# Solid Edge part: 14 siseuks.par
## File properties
Author: Henri
Template: Normal.par
Last saved by: Henri
Revision: 1
Application: Solid Edge
Accuracy: 0,990
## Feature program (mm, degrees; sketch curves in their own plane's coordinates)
sketch for "unnamed Protrusion 1" plane through (0, 0, 0) normal (1, 0, 0) x-axis (0, 1, 0)
  line (-25, -42.5) -> (-25, 54.5)
  arc centre (-22, 54.5) radius 3 from (-25, 54.5) to (-22, 57.5) cw
  line (-22, 57.5) -> (22, 57.5)
  arc centre (22, 54.5) radius 3 from (22, 57.5) to (25, 54.5) cw
  line (25, 54.5) -> (25, -42.5)
  line (25, -42.5) -> (-25, -42.5)
extrude "unnamed Protrusion 1" add finite 2.5 along +normal
sketch for "unnamed Cutout 1" plane through (2.5, 0, 0) normal (1, 0, 0) x-axis (0, 1, 0)
  line (-15, 41.5) -> (-15, 46)
  arc centre (-13.5, 46) radius 1.5 from (-15, 46) to (-13.5, 47.5) cw
  line (-13.5, 47.5) -> (13.5, 47.5)
  arc centre (13.5, 46) radius 1.5 from (13.5, 47.5) to (15, 46) cw
  line (15, 46) -> (15, 41.5)
  arc centre (13.5, 41.5) radius 1.5 from (13.5, 40) to (15, 41.5) ccw
  line (13.5, 40) -> (-13.5, 40)
  arc centre (-13.5, 41.5) radius 1.5 from (-15, 41.5) to (-13.5, 40) ccw
extrude "unnamed Cutout 1" cut through along -normal
sketch for "ExtrudedCutout_2" #1 plane through (2.5, 0, 0) normal (1, 0, 0) x-axis (0, 1, 0)
  line (14, 10) -> (-14, 10)
  arc centre (-14, 11) radius 1 from (-15, 11) to (-14, 10) ccw
  line (-15, 11) -> (-15, 34)
  arc centre (-14, 34) radius 1 from (-15, 34) to (-14, 35) cw
  line (-14, 35) -> (14, 35)
  arc centre (14, 34) radius 1 from (14, 35) to (15, 34) cw
  line (15, 34) -> (15, 11)
  arc centre (14, 11) radius 1 from (14, 10) to (15, 11) ccw
sketch for "ExtrudedCutout_2" #2 plane through (2.5, 0, 0) normal (1, 0, 0) x-axis (0, 1, 0)
  line (-14, -12.5) -> (14, -12.5)
  arc centre (14, -13.5) radius 1 from (15, -13.5) to (14, -12.5) ccw
  line (15, -13.5) -> (15, -36.5)
  arc centre (14, -36.5) radius 1 from (14, -37.5) to (15, -36.5) ccw
  line (14, -37.5) -> (-14, -37.5)
  arc centre (-14, -36.5) radius 1 from (-15, -36.5) to (-14, -37.5) ccw
  line (-15, -36.5) -> (-15, -13.5)
  arc centre (-14, -13.5) radius 1 from (-15, -13.5) to (-14, -12.5) cw
extrude "ExtrudedCutout_2" cut finite 1 along -normal
sketch for "ExtrudedCutout_3" #1 plane through (0, 0, 0) normal (-1, 0, 0) x-axis (0, -1, 0)
  line (15, -4) -> (15, 19)
  arc centre (14, 19) radius 1 from (15, 19) to (14, 20) ccw
  line (14, 20) -> (-14, 20)
  arc centre (-14, 19) radius 1 from (-14, 20) to (-15, 19) ccw
  line (-15, 19) -> (-15, -4)
  arc centre (-14, -4) radius 1 from (-15, -4) to (-14, -5) ccw
  line (-14, -5) -> (14, -5)
  arc centre (14, -4) radius 1 from (14, -5) to (15, -4) ccw
sketch for "ExtrudedCutout_3" #2 plane through (0, 0, 0) normal (-1, 0, 0) x-axis (0, -1, 0)
  line (15, -36.5) -> (15, -13.5)
  arc centre (14, -13.5) radius 1 from (15, -13.5) to (14, -12.5) ccw
  line (14, -12.5) -> (-14, -12.5)
  arc centre (-14, -13.5) radius 1 from (-14, -12.5) to (-15, -13.5) ccw
  line (-15, -13.5) -> (-15, -36.5)
  arc centre (-14, -36.5) radius 1 from (-14, -37.5) to (-15, -36.5) cw
  line (-14, -37.5) -> (14, -37.5)
  arc centre (14, -36.5) radius 1 from (14, -37.5) to (15, -36.5) ccw
extrude "ExtrudedCutout_3" cut finite 1 along -normal
sketch for "ExtrudedProtrusion_2" plane through (2.5, 0, 0) normal (1, 0, 0) x-axis (0, 1, 0)
  circle centre (20.4236, 0) radius 0.5
extrude "ExtrudedProtrusion_2" add finite 2 along +normal
sketch for "ExtrudedProtrusion_4" plane through (4.5, 20.4236, 0) normal (1, 0, 0) x-axis (0, 1, 0)
  arc centre (-2.4077, -6.4231) radius 7.3595 from (0.1755, 0.4682) to (-6.3062, -0.1809) ccw
  arc centre (-6.0968, -0.6638) radius 0.5264 from (-6.3062, -0.1809) to (-6.4593, -1.0456) ccw
  arc centre (-6.3215, -0.9005) radius 0.2 from (-6.4593, -1.0456) to (-6.1965, -1.0566) ccw
  arc centre (-2.7375, -5.3756) radius 5.5334 from (-6.1965, -1.0566) to (-0.2514, -0.4322) cw
extrude "ExtrudedProtrusion_4" add finite 1 along +normal
fillet "Round_1" radius 0.25
sketch for "ExtrudedProtrusion_7" plane through (0, 0, 0) normal (-1, 0, 0) x-axis (0, -1, 0)
  circle centre (-20.4236, 0) radius 0.5
extrude "ExtrudedProtrusion_7" add finite 2 along +normal
sketch for "ExtrudedProtrusion_8" plane through (-2, 20.4236, 0) normal (-1, 0, 0) x-axis (0, -1, 0)
  arc centre (2.4077, -6.4231) radius 7.3595 from (-0.1755, 0.4682) to (6.3062, -0.1809) cw
  arc centre (6.0968, -0.6638) radius 0.5264 from (6.3062, -0.1809) to (6.4593, -1.0456) cw
  arc centre (6.3215, -0.9005) radius 0.2 from (6.4593, -1.0456) to (6.1965, -1.0566) cw
  arc centre (2.7375, -5.3756) radius 5.5334 from (6.1965, -1.0566) to (0.2514, -0.4322) ccw
extrude "ExtrudedProtrusion_8" add finite 1 along +normal
fillet "Round_3" radius 0.25
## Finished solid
Body 1: solid body, 85 faces, 205 edges, 128 vertices.
  Faces by surface: plane 34, cylinder 32, torus 15, blend 4
  Edges by curve: line 104, circle 83, intersection 18
Bounding box of the edges (mm; curved faces can reach further): 8.500 x 50.000 x 100.000, from (-3, -25, -42.5) to (5.5, 25, 57.5).
Cylindrical faces by radius (mm): R0.2 x2, R0.5 x2, R0.5264 x2, R1 x16, R1.5 x4, R3 x2, R5.5334 x2, R7.3595 x2
Toroidal faces (ring radius, tube radius in mm): R0.25 r0.25 x2, R0.2764 r0.25 x4, R0.75 r0.25 x1, R5.7834 r0.25 x4, R7.1095 r0.25 x4
Planar faces by outward normal: +x 5, +y 6, +z 6, -x 5, -y 6, -z 6
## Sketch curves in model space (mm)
arc centre (-2, 14.3269, -0.6638) radius 0.5264 from (-2, 14.1175, -0.1809) through (-2, 13.806, -0.5876) to (-2, 13.9644, -1.0456)
arc centre (-2, 14.1021, -0.9005) radius 0.2 from (-2, 13.9644, -1.0456) through (-2, 14.0937, -1.1004) to (-2, 14.2271, -1.0566)
arc centre (-2, 17.6861, -5.3756) radius 5.5334 from (-2, 14.2271, -1.0566) through (-2, 17.1081, 0.1275) to (-2, 20.1722, -0.4322)
arc centre (-2, 20.4236, 0) radius 0.5 from (-2, 20.5991, 0.4682) through (-2, 20.8689, -0.2275) to (-2, 20.1722, -0.4322)
arc centre (-2, 18.0159, -6.4231) radius 7.3595 from (-2, 20.5991, 0.4682) through (-2, 17.2826, 0.8998) to (-2, 14.1175, -0.1809)
circle centre (0, 20.4236, 0) radius 0.5
arc centre (4.5, 14.3269, -0.6638) radius 0.5264 from (4.5, 14.1175, -0.1809) through (4.5, 13.806, -0.5876) to (4.5, 13.9644, -1.0456)
arc centre (4.5, 14.1021, -0.9005) radius 0.2 from (4.5, 13.9644, -1.0456) through (4.5, 14.0937, -1.1004) to (4.5, 14.2271, -1.0566)
arc centre (4.5, 17.6861, -5.3756) radius 5.5334 from (4.5, 14.2271, -1.0566) through (4.5, 17.1081, 0.1275) to (4.5, 20.1722, -0.4322)
arc centre (4.5, 20.4236, 0) radius 0.5 from (4.5, 20.5991, 0.4682) through (4.5, 20.8689, -0.2275) to (4.5, 20.1722, -0.4322)
arc centre (4.5, 18.0159, -6.4231) radius 7.3595 from (4.5, 20.5991, 0.4682) through (4.5, 17.2826, 0.8998) to (4.5, 14.1175, -0.1809)
circle centre (2.5, 20.4236, 0) radius 0.5
arc centre (0, 14, -4) radius 1 from (0, 15, -4) through (0, 14.6862, -4.7274) to (0, 14, -5)
line (0, 14, -5) -> (0, -14, -5)
arc centre (0, -14, -4) radius 1 from (0, -14, -5) through (0, -14.7274, -4.6862) to (0, -15, -4)
line (0, -15, -4) -> (0, -15, 19)
arc centre (0, -14, 19) radius 1 from (0, -15, 19) through (0, -14.6862, 19.7274) to (0, -14, 20)
line (0, -14, 20) -> (0, 14, 20)
arc centre (0, 14, 19) radius 1 from (0, 14, 20) through (0, 14.7274, 19.6862) to (0, 15, 19)
line (0, 15, 19) -> (0, 15, -4)
arc centre (0, 14, -36.5) radius 1 from (0, 14, -37.5) through (0, 14.7274, -37.1862) to (0, 15, -36.5)
line (0, 14, -37.5) -> (0, -14, -37.5)
arc centre (0, -14, -36.5) radius 1 from (0, -14, -37.5) through (0, -14.7274, -37.1862) to (0, -15, -36.5)
line (0, -15, -36.5) -> (0, -15, -13.5)
arc centre (0, -14, -13.5) radius 1 from (0, -15, -13.5) through (0, -14.6862, -12.7726) to (0, -14, -12.5)
line (0, -14, -12.5) -> (0, 14, -12.5)
arc centre (0, 14, -13.5) radius 1 from (0, 14, -12.5) through (0, 14.7274, -12.8138) to (0, 15, -13.5)
line (0, 15, -13.5) -> (0, 15, -36.5)
arc centre (2.5, 13.5, 46) radius 1.5 from (2.5, 13.5, 47.5) through (2.5, 14.5911, 47.0294) to (2.5, 15, 46)
line (2.5, 15, 46) -> (2.5, 15, 41.5)
arc centre (2.5, 13.5, 41.5) radius 1.5 from (2.5, 13.5, 40) through (2.5, 14.5911, 40.4706) to (2.5, 15, 41.5)
line (2.5, 13.5, 40) -> (2.5, -13.5, 40)
arc centre (2.5, -13.5, 41.5) radius 1.5 from (2.5, -15, 41.5) through (2.5, -14.5294, 40.4089) to (2.5, -13.5, 40)
line (2.5, -15, 41.5) -> (2.5, -15, 46)
arc centre (2.5, -13.5, 46) radius 1.5 from (2.5, -15, 46) through (2.5, -14.5294, 47.0911) to (2.5, -13.5, 47.5)
line (2.5, -13.5, 47.5) -> (2.5, 13.5, 47.5)
arc centre (2.5, 14, 34) radius 1 from (2.5, 14, 35) through (2.5, 14.7274, 34.6862) to (2.5, 15, 34)
line (2.5, 15, 34) -> (2.5, 15, 11)
arc centre (2.5, 14, 11) radius 1 from (2.5, 14, 10) through (2.5, 14.7274, 10.3138) to (2.5, 15, 11)
line (2.5, 14, 10) -> (2.5, -14, 10)
arc centre (2.5, -14, 11) radius 1 from (2.5, -15, 11) through (2.5, -14.6862, 10.2726) to (2.5, -14, 10)
line (2.5, -15, 11) -> (2.5, -15, 34)
arc centre (2.5, -14, 34) radius 1 from (2.5, -15, 34) through (2.5, -14.6862, 34.7274) to (2.5, -14, 35)
line (2.5, -14, 35) -> (2.5, 14, 35)
arc centre (2.5, 14, -13.5) radius 1 from (2.5, 15, -13.5) through (2.5, 14.6862, -12.7726) to (2.5, 14, -12.5)
line (2.5, 15, -13.5) -> (2.5, 15, -36.5)
arc centre (2.5, 14, -36.5) radius 1 from (2.5, 14, -37.5) through (2.5, 14.7274, -37.1862) to (2.5, 15, -36.5)
line (2.5, 14, -37.5) -> (2.5, -14, -37.5)
arc centre (2.5, -14, -36.5) radius 1 from (2.5, -15, -36.5) through (2.5, -14.6862, -37.2274) to (2.5, -14, -37.5)
line (2.5, -15, -36.5) -> (2.5, -15, -13.5)
arc centre (2.5, -14, -13.5) radius 1 from (2.5, -15, -13.5) through (2.5, -14.6862, -12.7726) to (2.5, -14, -12.5)
line (2.5, -14, -12.5) -> (2.5, 14, -12.5)
arc centre (0, 22, 54.5) radius 3 from (0, 22, 57.5) through (0, 24.1821, 56.5587) to (0, 25, 54.5)
line (0, 25, 54.5) -> (0, 25, -42.5)
line (0, 25, -42.5) -> (0, -25, -42.5)
line (0, -25, -42.5) -> (0, -25, 54.5)
arc centre (0, -22, 54.5) radius 3 from (0, -25, 54.5) through (0, -24.0587, 56.6821) to (0, -22, 57.5)
line (0, -22, 57.5) -> (0, 22, 57.5)
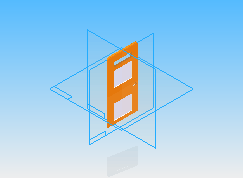
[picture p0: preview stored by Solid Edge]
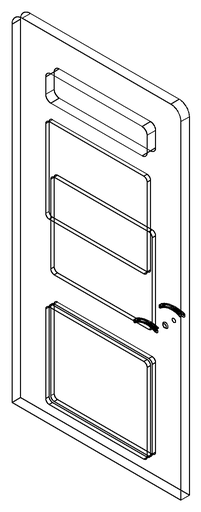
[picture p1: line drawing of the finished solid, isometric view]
